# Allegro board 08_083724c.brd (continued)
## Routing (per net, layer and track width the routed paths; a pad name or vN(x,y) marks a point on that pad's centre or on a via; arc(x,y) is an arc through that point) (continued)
VDD_EXT: length 164.8
  TOP w0.14: U1.T12 v1(40.55,54.22) ; U1.K7 v1(45.35,48.62) ; U1.T10 v1(42.95,54.22) ; U1.T22 v1(32.55,53.42) ; U1.H7 v1(45.35,47.02) U1.G7 ; U1.H16 v1(37.35,47.02) ; U1.T14 v1(38.95,54.22) ; U1.P16 v1(37.35,52.62) ; U1.M7 v1(45.35,51.02) ; U1.P7 v1(45.35,52.62) ; U1.M16 v1(37.35,51.02)
  TOP w0.203: U1.K16 v1(37.35,49.42) ; C62.2 16.64,5.83 U9.A2
  TOP w0.305: C1.2 45.25,24.22 v1(45.25,25.1) ; v1(45.25,34.7) 45.04,34.91 C7.2 ; C8.2 37.66,34.91 v1(37.45,34.7) ; U4.21 42.11,4.75 41.98,4.61
  TOP w0.381: C62.2 16.32,8.17 TP23.1 ; v2(17.78,1.17) 18.1,1.49 R155.1 ; R154.1 v2(32.65,18.08) ; R66.1 v2(7.57,6.02)
  TOP w0.508: C54.2 22.15,40.68 v2(22.15,39.83) ; v2(75.79,60.12) C96.1 75.14,60.82 74.69,60.37 U15.4 ; v2(63.55,63.4) 63.58,63.42 v2(64.4,63.42) 64.41,63.43 R132.1 R133.1 R134.1 R135.1 ; R9.1 v2(27.1,40.78) ; R117.1 v2(60.72,59.11) ; v2(68.17,60.26) C242.1 66.94,59.81 U17.4 ; R96.1 v2(70.69,59.42) ; DS9.A 70.92,63.57 v2(70.56,63.21) R95.1 ; R139.1 v2(52.65,61.63) ; R139.1 R140.1 ; R139.1 R138.1 ; R140.1 R141.1 v2(54.94,61.63) ; R140.1 v2(53.8,61.63) ; R83.1 v2(78.31,26.98) ; 16.46,10.04 P10.2 ; P10.2 18.23,11.81 ; P10.2 16.46,11.81 ; P10.2 18.23,10.04 ; v2(63.14,41) 61.7,41 S2.C1 ; Y2.4 54.69,43.11 C241.2 v2(53.94,43.1) ; R109.2 15.82,20.99 15.82,14.78 ; v2(39.45,4.61) C55.1 C53.1 41.98,4.61 ; DS11.A 62.05,51.46 v2(64.35,51.46) ; R115.1 v2(60.72,62.4) ; DS3.A v2(43.64,13.86) ; R101.1 57.73,43.15 v2(57.47,42.89) ; R137.1 R138.1 ; R137.1 R136.1 49.23,61.7 ; R137.1 50.37,61.65 ; R138.1 v2(51.51,61.63) ; C5.1 v2(41.48,20.52) ; DS6.A 21.65,46.94 v2(21.65,47.32) ; R81.1 v2(75.64,29.76) ; v2(12.14,6.53) C32.2 11.39,6.51 U19.5 ; R17.1 39.96,5.38 v2(39.45,5.38) ; R39.1 v2(64.09,31.04) ; DS4.A v2(45.29,13.86) ; S2.C2 v2(71.63,40.69) ; v2(14.74,55.93) 16.24,55.93 DS5.A ; v2(22.15,52.91) 22.15,53.63 C58.2 ; DS2.A v2(41.99,13.86) ; R8.1 v2(27.2,44.88)
  L6_PWR1 w0.508: P10.2 18.23,11.81 ; P10.2 18.23,10.04 ; P10.2 16.46,11.81 ; P10.2 16.46,10.04
  BOTTOM w0.14: U3.F12 v1(37.45,25.1) ; U10.N4 U10.P3
  BOTTOM w0.175: U10.P5 36.4,13.71 35.92,13.24 U10.N4
  BOTTOM w0.203: 26.31,10.58 26.29,10.6 U8.14 ; U7.14 29.53,18.09 29.55,18.07 ; v1(37.35,51.02) 37.17,51.02 36.44,50.28 C170.1 37.23,49.42 v1(37.35,49.42)
  BOTTOM w0.229: U10.N4 v1(35.92,12.71) ; U10.P3 v1(35.42,14.39) ; U10.P5 v1(36.42,14.39)
  BOTTOM w0.305: v1(37.45,25.1) 37.45,23.19 C3.2 ; U3.G4 v1(38.75,31.5) ; U3.G9 v1(38.75,28.3) ; U13.8 v2(74.33,19.19) ; U3.T4 v1(43.95,31.5) ; U5.D1 17.77,42.33 ; U5.B4 v2(22.15,39.83) ; U3.T9 v1(43.95,28.3) ; R123.1 v2(74.31,55.68) ; U3.F1 v1(37.45,34.7) ; U29.14 78.23,30.61 78.57,30.27 ; U3.U1 v1(45.25,34.7) ; U22.21 61.15,22.65 C254.1 ; U5.E4 21.65,44.75 ; U22.17 57.72,26.46 C256.1 ; R113.1 v2(74.75,56.95) ; v2(66.88,53.14) 66.88,53.61 66.57,53.91 U21.4 ; U3.U12 v1(45.25,25.1) ; R159.1 v2(60.66,56.31) ; C167.1 45.35,50.78 v1(45.35,51.02) ; R127.1 67.77,56.28 68.07,56.58 U18.5 69.62,56.58 69.93,56.89 69.93,57.83 C125.1 ; U13.1 78.23,12.83 78.54,13.14 C90.1
  BOTTOM w0.33: U6.B4 v2(22.15,52.91)
  BOTTOM w0.508: C253.1 62.43,22.91 R207.2 ; C253.1 C254.1 ; C253.1 v2(63.32,22.92) ; v2(21.65,47.32) C57.2 21.65,44.76 ; R129.1 v2(69.42,54) ; v2(15.71,42.33) C56.2 16.51,42.33 17.77,42.33 ; P10.2 18.23,10.04 ; P10.2 16.46,10.04 ; P10.2 16.46,11.81 ; P10.2 18.23,11.81 ; v2(30.01,18.86) C59.1 29.55,18.07 ; R47.1 v2(26.56,54.79) ; R14.1 v2(79.71,59.29) ; R48.1 v2(26.56,55.93) ; v2(26.77,11.37) C60.1 26.31,10.58 ; E3.2 53.77,52.36 C164.1 55.91,52.16 v2(57.19,52.16) ; R18.1 v2(13.6,41.32) ; C125.1 v2(69.18,57.84) ; v2(64.57,12.5) C262.1 63.68,12.52 Y4.4 Y4.1 ; C256.1 C255.1 v2(59,25.96) ; R20.1 v2(23.18,36.11) ; R46.1 v2(14.74,55.93) ; C137.1 v2(64.35,51.46) ; v1(32.55,53.42) 32.53,53.39 C171.1 ; 78.57,30.27 C87.1 v2(79.45,31.04) 79.71,31.29 R4.1 ; JP2.1 v2(79.71,45.19) R10.1 ; R44.1 v2(14.74,53.9) ; R145.1 v2(13.6,42.35) ; R38.1 v2(17.03,36.11) ; C90.1 v2(79.45,12.39)
  vias: v1(36.92,8.21) v2(14.55,10.72) v2(14.55,9.96) v2(14.55,9.19) v2(14.55,8.43) v2(15.32,10.72) v2(15.32,9.96) v2(15.32,9.19) v2(15.32,8.43) v2(23.77,50.52) v2(23.77,49.91) v2(26.24,48.98) v2(63.13,40.12)
VDD_INPUT: length 1.7
  BOTTOM w0.254: v2(6.43,43.1) 6.74,43.42 U2.1
  vias: v2(2.24,43.36) v2(2.24,42.6) v2(2.24,41.83) v2(3,43.36) v2(6.43,51.87) v2(6.93,51.87) v2(7.44,51.87) v2(7.95,51.87) v2(10.87,42.72) v2(10.87,41.96) v2(11.63,42.72) v2(11.63,41.96) v2(48.97,23.93) v2(48.97,23.29) v2(49.61,23.93) v2(49.61,23.29)
VDD_INT: length 78.6
  TOP w0.14: U1.J12 v1(40.55,48.62) ; U1.P10 v1(42.95,52.62) ; v1(43.75,51.02) U1.M9 v1(42.95,50.22) ; U1.P12 v1(40.55,52.62) ; U1.P15 v1(38.15,52.62) ; U1.K15 v1(38.15,49.42) ; U1.P8 v1(44.55,52.62) ; U1.R12 v1(40.55,53.42) ; U1.K8 v1(44.55,49.42) ; U1.J8 v1(44.55,48.62) ; U1.K13 v1(39.75,49.42) ; U1.M13 v1(39.75,51.02) ; U1.L15 v1(38.15,50.22) ; U1.R8 v1(44.55,53.42) ; U1.R15 v1(38.15,53.42) ; U1.N8 v1(44.55,51.82) ; U1.K9 v1(43.75,49.42) ; U1.R9 v1(43.75,53.42) ; U1.M8 v1(44.55,51.02) ; U1.T8 v1(44.55,54.22) ; U1.P13 v1(39.75,52.62) ; U1.M15 v1(38.15,51.02) ; U1.K14 v1(38.95,49.42) ; U1.J14 v1(38.95,48.62) ; U1.R14 v1(38.95,53.42) ; U1.P11 v1(42.15,52.62) ; U1.R11 v1(42.15,53.42) ; U1.J11 v1(41.35,48.62) ; U1.J9 v1(43.75,48.62) ; U1.L8 v1(44.55,50.22) ; U1.M12 v1(40.55,51.02) ; U1.R10 v1(42.95,53.42) ; U1.P9 v1(43.75,52.62) ; U1.M14 v1(38.95,51.02) ; U1.K12 v1(41.35,49.42) ; U1.N15 v1(38.15,51.82) ; U1.P14 v1(38.95,52.62) ; U1.J15 v1(38.15,48.62) ; U1.R13 v1(39.75,53.42)
  TOP w0.305: v1(47.32,62.41) 46.93,62.02 C190.1
  TOP w0.508: C185.1 v2(53.77,58.87) ; C193.1 v2(31.54,56.07) ; C192.1 v2(31.54,54.57) ; v2(32.23,60.63) 32.23,61.13 32.74,61.64 C184.1 33.24,61.62 C187.1 ; v2(51.27,53.99) C188.1 C191.1 ; P7.2 25.09,27.48 ; P7.2 25.09,25.71 ; P7.2 23.32,27.48 ; P7.2 23.32,25.71 ; R131.2 15.38,24.69 15.89,25.2 20.65,25.2 ; C194.1 v2(31.54,57.58) ; C186.1 v2(53.77,57.2) ; C190.1 48.06,61.57 C189.1 v2(48.07,62.29) ; 20.65,27.99 15.89,27.99 15.38,28.5 R125.2 ; C206.1 v2(31.55,58.98)
  L7_PWR2 w0.508: P7.2 25.09,27.48 ; P7.2 23.32,25.71 ; P7.2 25.09,25.71 ; P7.2 23.32,27.48
  BOTTOM w0.14: v1(42.95,50.22) 42.95,50.14 C215.1
  BOTTOM w0.305: v1(47.32,62.41) 46.93,62.02 C190.1
  BOTTOM w0.508: C194.1 v2(31.54,57.58) ; C190.1 48.06,61.57 C189.1 v2(48.07,62.29) ; C195.1 v2(26.85,59.36) ; P7.2 25.09,25.71 ; P7.2 25.09,27.48 ; P7.2 23.32,25.71 ; P7.2 23.32,27.48 ; C186.1 v2(53.77,57.2) ; C206.1 v2(31.55,58.98) ; C193.1 v2(31.54,56.07) ; v2(32.23,60.63) C198.1 31.2,61.13 31.71,61.64 C184.1 34.34,61.64 C187.1 ; C185.1 v2(53.77,58.87) ; C197.1 v2(26.85,57.84) ; C188.1 v2(51.27,53.99) ; C192.1 v2(31.54,54.57)
  vias: v2(24.97,31.17) v2(24.97,30.4) v2(24.97,29.64) v2(24.97,28.88) v2(25.73,31.17) v2(25.73,30.4) v2(25.73,29.64) v2(25.73,28.88)
VDD_LPDD4_IO: length 115.8
  TOP w0.14: U1.E8 v1(44.55,44.62) ; U1.E11 v1(42.15,44.62) ; U1.G11 v1(42.15,47.02) ; U1.E13 v1(39.75,44.62) ; U1.F15 v1(38.15,46.22) ; U1.E12 v1(40.55,44.62) ; U1.E9 v1(43.75,44.62) ; U1.D13 v1(39.75,43.82) ; U1.F9 v1(43.75,46.22) ; U1.G9 v1(43.75,47.02) ; U1.D14 v1(38.95,43.82) ; U1.F8 v1(44.55,46.22) ; U1.D10 v1(42.95,43.82) ; U1.G15 v1(38.15,47.02) ; U1.G12 v1(40.55,47.02) ; U1.G14 v1(38.95,47.02) ; U1.E15 v1(38.15,44.62) ; U1.F14 v1(38.95,46.22) ; U1.E14 v1(38.95,44.62) ; U1.D11 v1(42.15,43.82) ; U1.G8 v1(44.55,47.02) ; U1.G13 v1(39.75,47.02) ; U1.D9 v1(43.75,43.82) ; U1.F10 v1(42.95,46.22) ; U1.E10 v1(42.95,44.62) ; U1.G10 v1(42.95,47.02)
  TOP w0.203: v1(42,34.7) 42,35.34 C16.2 ; v1(40.05,25.1) 40.05,24.46 C17.2 ; v1(40.7,34.7) 40.7,35.34 C18.2 ; v1(42,25.1) 42,25.43 C11.2
  TOP w0.305: R148.2 43.01,34.99 v1(43.3,34.7) ; 44.92,30.4 45.21,30.7 v1(45.25,30.7) ; v1(45.25,29.1) 45.21,29.1 44.92,29.39 ; R149.2 39.69,34.99 v1(39.4,34.7) ; v1(42,33.1) 41.5,33.1 C117.2 41.2,33.1 v1(40.7,33.1)
  TOP w0.508: 1.98,11.81 2.87,10.92 ; 2.87,10.92 3.76,11.81 ; 2.87,10.92 3.76,10.04 ; 2.87,10.92 1.98,10.04 ; R16.1 v2(33.35,29.72) ; C14.1 v2(37.8,20.52) ; C146.1 v2(45.03,20.52) ; R106.2 4.39,20.99 4.39,14.78
  BOTTOM w0.14: U3.F10 v1(37.45,26.7) ; U3.N10 v1(42.65,26.7) ; U3.K10 v1(40.05,26.7) ; U3.U8 v1(45.25,29.1) ; U3.AA10 v1(47.85,26.7) ; U3.F8 v1(37.45,29.1) ; U3.AA8 v1(47.85,29.1) ; U3.R8 v1(43.3,28.3) ; U3.B10 v1(34.85,26.7) ; U3.R12 v1(43.3,25.1) ; U3.B8 v1(34.85,29.1) ; U3.N3 v1(42,33.1) ; U3.W8 v1(46.55,29.1) ; U3.H8 v1(39.4,29.1) ; U3.U3 v1(45.25,33.1) ; U3.U10 v1(45.25,26.7) ; U3.D8 v1(36.15,29.1)
  BOTTOM w0.305: U3.R1 v1(43.3,34.7) 43.3,35.34 43.77,35.81 C50.2 ; C22.2 40.84,34.83 v1(40.7,34.7) U3.K1 ; C101.2 C102.2 49.73,27.86 49.36,27.5 v1(48.5,27.5) U3.AB9 ; U3.D1 v1(36.15,34.7) 36.15,35.69 36.03,35.81 C162.2 ; U3.R5 v1(43.3,30.7) ; U3.D5 v1(36.15,30.7) ; C152.2 42,23.17 v1(42,25.1) U3.N12 ; C23.2 41.87,34.83 v1(42,34.7) U3.N1 ; U3.K12 v1(40.05,25.1) 40.05,23.19 C153.2 ; U3.B5 v1(34.85,30.7) ; 44.15,23.16 44.15,23.8 43.3,24.64 v1(43.3,25.1) ; U3.H12 v1(38.75,25.1) 38.75,23.22 C154.2 ; U3.W12 v1(46.55,25.1) 46.55,23.16 C150.2 ; C155.2 36.15,23.16 v1(36.15,25.1) U3.D12 ; U3.F3 v1(37.45,33.1) ; U3.AA5 v1(47.85,30.7) ; U3.AB4 v1(48.5,32.3) 49.49,32.3 49.86,31.93 C98.2 C52.2 ; U3.A9 v1(34.2,27.5) 33.72,27.5 33.35,27.86 C157.2 ; U3.AA3 v1(47.85,32.3) ; U3.K3 v1(40.7,33.1) ; C51.2 46.68,35.73 46.55,35.6 v1(46.55,34.7) U3.W1 ; C49.1 41.04,40.5 C115.1 41.41,40.5 C46.1 v1(42.24,40.93) ; U3.H1 v1(39.4,34.7) 39.4,35.34 38.93,35.81 C21.2 ; U3.U5 v1(45.25,30.7) ; U3.F5 v1(37.45,30.7) ; U3.B3 v1(34.85,32.3) ; U3.H5 v1(39.4,30.7) ; U3.W5 v1(46.55,30.7) ; U3.A4 v1(34.2,32.3) 33.72,32.3 33.35,31.93 C160.2
  BOTTOM w0.508: C102.2 C103.2 C100.2 C98.2 ; C156.2 C157.2 C158.2 C159.2 C160.2 C161.2 ; 2.87,10.92 3.76,10.04 ; 2.87,10.92 3.76,11.81 ; 2.87,10.92 1.98,11.81 ; 2.87,10.92 1.98,10.04 ; v2(52.15,38.15) 50.62,39.68 R150.1
  vias: v2(5.69,11.59) v2(5.69,10.89) v2(5.69,10.19) v2(6.39,11.59) v2(6.39,10.89) v2(6.39,10.19) v2(7.09,11.59) v2(7.09,10.89) v2(7.09,10.19) v2(30.42,38.4) v2(30.42,37.39) v2(52.15,37.13)
VDD_SOM: length 0.8
  BOTTOM w0.508: R164.1 v2(12.4,57.07)
  vias: v2(2.71,66.33) v2(2.71,65.63) v2(2.71,64.93) v2(3.41,66.33) v2(3.41,65.63) v2(3.41,64.93) v2(4.11,66.33) v2(4.11,65.63) v2(4.11,64.93)
_N14: length 18.4
  TOP w0.14: U1.K10 v1(42.95,49.42) ; U1.K11 v1(42.15,49.42) ; U1.M10 v1(42.15,51.02) ; U1.M11 v1(41.35,51.02)
  L3_SIG1 w0.267: v1(42.15,49.42) 42.15,49.59 42.56,50.01 42.56,50.6 v1(42.15,51.02)
  L8_SIG3 w0.267: v1(42.15,49.42) v1(42.95,49.42) ; v1(41.35,51.02) v1(42.15,51.02) 42.99,51.02 43.38,50.63 44.93,50.63 45.34,50.22 v1(46.15,50.22)
  BOTTOM w0.508: E3.1 52.02,52.34 C26.1 51.82,49.95 C27.1 49.98,50.22 v1(46.15,50.22)
_N15: length 4.7
  TOP w0.14: R143.2 53.29,51.6 C25.1 55.76,51.6 55.9,51.47 v2(55.9,50.93)
  BOTTOM w0.14: R158.1 56.85,50.8 56.71,50.93 v2(55.9,50.93)
_N16: length 6.6
  TOP w0.14: R142.1 54.3,48.06 C24.1 54.69,47.68 56.84,47.68 57.8,48.63 v2(57.8,48.73)
  BOTTOM w0.14: v2(57.8,48.73) 56.98,48.73 56.85,48.87 R158.2
_N31: length 5.8
  TOP w0.14: U1.R22 v1(32.55,52.62)
  BOTTOM w0.508: v1(32.55,52.62) 32.3,52.37 C29.1 30.42,52.37 29.91,51.85 C28.1 27.85,51.8 E4.1
_N36: length 16.4
  TOP w0.14: U1.F12 v1(40.55,46.22)
  L6_PWR1 w0.229: v1(40.55,46.22) 41.26,46.22 42.46,45.02 45.53,45.02 45.75,44.8 45.75,42.74 45.88,42.62 47.2,42.62 47.35,42.46 47.35,41.98 47.52,41.82 51.71,41.82 v2(52.65,40.88)
_N50: length 3.5
  BOTTOM w0.14: JP2.2 79.71,48.56 79.2,49.07 P5.1
_N51: length 1.7
  BOTTOM w0.14: P5.10 76.78,55.68 JP1.2
_N72: length 6.1
  TOP w0.14: R153.1 29.47,46.6 30.66,46.6 32.68,48.62 33.35,48.62 U1.K21
_N74: length 4.7
  TOP w0.14: TP24.1 30.66,50.24 34.18,50.24 U1.M20
_N82: length 4.7
  BOTTOM w0.14: R43.2 R45.1 18.75,52.5 U6.B2
_N89: length 10.5
  TOP w0.14: v2(34.49,20.05) 34.49,20.05 R52.2
  L3_SIG1 w0.114: v2(34.49,20.05) 36.33,18.21 36.33,15.86 37.34,14.86 37.34,12.66 v1(36.92,12.24)
  BOTTOM w0.14: U10.M6 v1(36.92,12.24)
_N100: length 4.2
  TOP w0.305: v1(34.92,8.21) 34.54,8.21 34.24,7.91 34.24,6.45 35.18,5.51 C64.2
_N101: length 2.1
  BOTTOM w0.14: R50.1 29.3,19.01 29.3,18.77 29.02,18.49 U7.13
_N102: length 14
  TOP w0.14: v2(33.48,20.12) 33.48,19.24 R52.1
  L5_SIG2 w0.114: v2(28.28,14.27) 32.08,14.27 33.48,15.67 v2(33.48,20.12)
  BOTTOM w0.14: v2(28.28,14.27) 28.28,16.04 27.85,16.47 U7.1
_N105: length 2.4
  BOTTOM w0.14: U8.13 25.78,11 26.06,11.28 26.06,12.06 26.23,12.23 R51.1
_N108: length 13.5
  L8_SIG3 w0.114: v1(35.42,6.74) 28.56,6.74 28.14,7.16 v2(25.04,7.16)
  BOTTOM w0.14: U10.A3 v1(35.42,6.74) ; U8.1 24.62,8.91 25.04,8.49 v2(25.04,7.16)
_N109: length 2.7
  TOP w0.14: U19.4 12.97,3.16 R57.2 R60.2
_N110: length 16.7
  L8_SIG3 w0.114: v1(35.92,6.4) 35.9,6.38 28.29,6.38 27.99,6.68 23.36,6.68 v2(22.88,7.16)
  BOTTOM w0.14: U8.4 23.42,8.96 22.88,8.42 v2(22.88,7.16) ; U10.A4 v1(35.92,6.4)
_N111: length 18
  L5_SIG2 w0.114: v2(22.08,11.64) 24.4,11.64 26.62,9.42 32.56,9.42 34.82,7.16 36,7.16 v1(36.42,6.74)
  BOTTOM w0.14: v2(22.08,11.64) 22.08,11.14 22.22,11 U8.8 ; U10.A5 v1(36.42,6.74)
_N112: length 15.6
  L5_SIG2 w0.114: v1(34.92,7.71) 32.8,9.83 26.82,9.83 24.4,12.26 v2(24.4,13.32)
  BOTTOM w0.14: U8.11 24.22,12.51 24.4,12.69 v2(24.4,13.32)
_N113: length 18.4
  TOP w0.14: U9.B1 15.87,4.51 15.32,5.07 v1(15.32,5.38)
  L3_SIG1 w0.114: v2(24.4,14.47) 23.63,14.47 15.32,6.15 v1(15.32,5.38)
  BOTTOM w0.14: U8.12 24.62,12.14 25.1,12.62 25.1,13.77 v2(24.4,14.47)
_N114: length 11.9
  TOP w0.14: U9.A1 16.24,5.38 v1(16.23,5.38)
  L3_SIG1 w0.114: v1(16.23,5.38) 17.25,6.4 18.87,6.4 23.19,10.72 v2(23.19,12.12)
  BOTTOM w0.14: v2(23.19,12.12) 23.42,11.89 U8.9
_N115: length 12.6
  TOP w0.14: U9.E1 16.02,3.1 v1(15.76,3.1)
  L3_SIG1 w0.114: v1(15.76,3.1) 16.17,2.69 18.21,2.69 18.85,3.33 18.85,3.91 22.99,8.05 v2(23.51,8.05)
  BOTTOM w0.14: U8.3 23.82,8.36 v2(23.51,8.05)
_N116: length 16.6
  TOP w0.14: U9.D1 16.13,3.61 v1(15.76,3.61)
  L3_SIG1 w0.114: v2(25.87,8.93) 25.64,8.5 19.51,2.37 15.79,2.37 15.27,2.9 15.27,3.49 15.38,3.61 v1(15.76,3.61)
  BOTTOM w0.14: v2(25.87,8.93) 25.87,9.63 25.69,9.8 U8.16
_N117: length 19.9
  TOP w0.14: 16.24,4.11 v1(15.78,4.11)
  L3_SIG1 w0.114: v2(26.82,14.64) 26.82,13.87 26.49,13.54 25.5,13.54 24.71,12.75 22.43,12.75 15.78,6.11 v1(15.78,4.11)
  BOTTOM w0.14: v2(26.82,14.64) 26.82,15.56 27.05,15.8 U7.3
_N118: length 21.2
  L3_SIG1 w0.114: v1(16.64,3.71) 16.29,3.71 16.18,3.83 16.18,4.62 17.47,5.92 19.09,5.92 25.54,12.37 26.11,12.37 27.36,13.61 27.36,14.82 v2(29.22,16.69)
  BOTTOM w0.14: v2(29.22,16.69) 29.22,17.07 29,17.29 U7.16
_N119: length 10.2
  L8_SIG3 w0.114: v1(17.04,3.71) 17.04,2.9 17.73,2.21 24.28,2.21 v2(25.1,1.39)
  BOTTOM w0.14: R53.1 v2(25.1,1.39)
_N121: length 2.2
  TOP w0.14: P6.5 v2(25.3,4)
  BOTTOM w0.14: R53.2 25.1,3.79 v2(25.3,4)
_N123: length 11.8
  TOP w0.14: U9.C4 v1(17.86,4.11)
  L5_SIG2 w0.114: v2(27.38,1.39) 26.11,2.67 19.68,2.67 18.24,4.11 v1(17.86,4.11)
  BOTTOM w0.14: R54.1 v2(27.38,1.39)
_N124: length 8
  TOP w0.14: v1(17.86,3.61) 17.55,3.61 U9.D4
  L5_SIG2 w0.114: v1(17.86,3.61) 18.19,3.61 19.48,2.31 22.91,2.31 v2(23.83,1.39)
  BOTTOM w0.14: R55.1 v2(23.83,1.39)
_N125: length 6.6
  TOP w0.14: v1(17.86,3.1) 17.66,3.1 U9.E4
  L5_SIG2 w0.114: v2(22.56,1.39) 22.08,1.87 19.09,1.87 v1(17.86,3.1)
  BOTTOM w0.14: R58.1 v2(22.56,1.39)
_N126: length 15.7
  TOP w0.14: v1(17.49,5.37) 17.44,5.32 U9.A4
  L5_SIG2 w0.114: v2(29.92,1.39) 27.86,3.45 21.39,3.45 19.96,4.88 19.38,4.88 18.44,5.82 17.78,5.82 17.67,5.7 v1(17.49,5.37)
  BOTTOM w0.14: R56.1 v2(29.92,1.39)
_N127: length 14.4
  TOP w0.14: U9.B4 17.69,4.51 17.86,4.69 17.86,5.19 v1(18.05,5.38)
  L5_SIG2 w0.114: v2(28.65,1.39) 26.97,3.07 21.11,3.07 19.89,4.29 18.77,4.29 18.05,5.02 v1(18.05,5.38)
  BOTTOM w0.14: R59.1 v2(28.65,1.39)
_N128: length 3.2
  TOP w0.14: R57.1 14.42,3.61 v2(14.81,3.86)
  L5_SIG2 w0.114: v2(14.81,3.86) 15.46,4.51 v1(16.64,4.51)
_N130: length 2.4
  TOP w0.14: P6.7 v2(23.1,4)
  BOTTOM w0.14: v2(23.1,4) 23.38,3.72 23.38,3.54 R55.2
_N131: length 2.3
  TOP w0.14: P6.8 v2(22,4)
  BOTTOM w0.14: R58.2 22,3.64 v2(22,4)
_N132: length 30.3
  TOP w0.14: v2(7.57,3.23) R66.2 7.58,4.11 9.09,4.11
  TOP w0.508: P6.10_1 P6.10_2 21.06,15.51 v2(21.03,15.48)
  L3_SIG1 w0.114: v2(7.57,3.23) 10.49,3.23 14.81,7.54 16.21,7.54 21.03,12.37 v2(21.03,15.48)
_N133: length 2.5
  TOP w0.14: P6.2 v2(28.6,3.99)
  BOTTOM w0.14: R59.2 28.6,3.14 v2(28.6,3.99)
_N140: length 2.2
  TOP w0.14: P6.3 v2(27.5,4)
  BOTTOM w0.14: v2(27.5,4) 27.5,3.21 R54.2
_N144: length 2.2
  TOP w0.14: P6.1 v2(29.7,4)
  BOTTOM w0.14: R56.2 29.7,3.31 v2(29.7,4)
_N147: length 4.5
  BOTTOM w0.14: R49.1 R46.2 19.13,55.93 U6.D2
_N177: length 5.2
  TOP w0.14: U1.K22 32.47,49.02 30.75,47.29 TP27.1 29.48,47.99 29.21,47.99 R11.1
_N243: length 13.4
  TOP w0.508: v2(73.24,58.22) S4.3 S4.4
  BOTTOM w0.14: v2(73.24,58.22) 72.53,57.51 R113.2 72.16,56.58 U18.1
_N244: length 2.4
  TOP w0.305: R160.1 DS11.C
_N245: length 1.5
  BOTTOM w0.14: R129.2 67.65,54.03 67.26,54.41 U21.3
_N246: length 1.5
  BOTTOM w0.14: U21.6 63.45,54.41 R130.1
_N247: length 3.1
  BOTTOM w0.14: U18.4 67.82,55.28 R127.2 67.45,54.91 U21.2
_N248: length 1.5
  BOTTOM w0.14: C127.1 63.32,54.91 U21.7
_N254: length 2.6
  BOTTOM w0.203: 7.44,58.86 U20.5
  BOTTOM w0.254: R167.2 7.44,58.86
  BOTTOM w0.381: R167.2 R105.1
_N255: length 3.2
  BOTTOM w0.203: U20.6 7.94,58.22 8.14,58.42 9.39,58.42 R107.1
  BOTTOM w0.381: R168.2 10.49,58.21 R107.1
_N256: length 3.2
  BOTTOM w0.203: R111.2 4.99,58.43 6.29,58.43 6.44,58.28 U20.3
  BOTTOM w0.381: R169.2 3.89,58.21 R111.2
_N257: length 2.6
  BOTTOM w0.203: 6.94,58.86 U20.4
  BOTTOM w0.254: R166.2 6.94,58.86
  BOTTOM w0.381: R165.1 R166.2
_N258: length 1.4
  BOTTOM w0.203: U20.10 7.44,54.68 R170.2
_N259: length 1.4
  BOTTOM w0.203: U20.11 6.94,54.68 C250.1
_N260: length 7.2
  L10_SIG4 w0.381: v2(5.61,57.17) 5.61,59.21 v2(4.58,60.24)
  BOTTOM w0.381: U20.2 v2(5.61,57.17) 4.81,57.17 R111.1 3.89,57.21 R163.2
  BOTTOM w0.508: R165.2 v2(4.58,60.24)
_N261: length 7.2
  L10_SIG4 w0.381: v2(9.79,60.24) 8.76,59.21 v2(8.76,57.17)
  BOTTOM w0.381: U20.7 v2(8.76,57.17) 9.56,57.17 R107.2 10.49,57.21 R164.2
  BOTTOM w0.508: R105.2 v2(9.79,60.24)
_N282: length 3.5
  BOTTOM w0.14: P4.1 79.2,35.36 79.71,34.85 R4.2
_N283: length 1.7
  BOTTOM w0.14: R5.2 76.78,41.58 P4.10
_N287: length 2.4
  TOP w0.305: R102.1 72.9,64.12 DS9.C
_N296: length 1.9
  TOP w0.381: R7.1 26.84,46.02 DS1.C
_N299: length 3.5
  BOTTOM w0.508: P9.1 4.05,13.46 ; P9.1 2.87,14.64 ; P9.1 1.69,13.46
_N308: length 2.4
  BOTTOM w0.305: v2(13.67,29.51) 13.67,28.63 13.07,28.03 U16.9
_N321: length 17
  TOP w0.14: U14.26 v2(65.28,23.41)
  L3_SIG1 w0.114: v2(75.39,16.37) 74.98,16.78 69.26,16.78 65.58,20.45 65.58,23.11 v2(65.28,23.41)
  BOTTOM w0.14: v2(75.39,16.37) 75.63,16.61 U13.10
_N322: length 19.2
  TOP w0.14: U14.25 v2(64.78,23.91)
  L3_SIG1 w0.114: v2(76.28,16.37) 75.55,17.1 69.39,17.1 65.93,20.56 65.93,23.56 65.57,23.91 v2(64.78,23.91)
  BOTTOM w0.14: v2(76.28,16.37) 76.28,16.38 U13.11
_N323: length 20.8
  TOP w0.14: v2(77.17,16.37) 77.11,16.37 76.58,16.9 R89.2 ; U14.24 v2(65.28,24.41)
  L3_SIG1 w0.114: v2(77.17,16.37) 76.11,17.43 69.51,17.43 66.24,20.69 66.24,23.99 65.82,24.41 v2(65.28,24.41)
  BOTTOM w0.14: v2(77.17,16.37) 76.93,16.6 U13.12
_N324: length 22.6
  TOP w0.14: U14.23 v2(64.78,24.91) ; v2(77.93,16.37) R88.2
  L3_SIG1 w0.114: v2(77.93,16.37) 76.53,17.77 69.62,17.77 66.56,20.82 66.56,24.22 65.87,24.91 v2(64.78,24.91)
  BOTTOM w0.14: U13.13 77.58,16.72 v2(77.93,16.37)
_N325: length 3
  TOP w0.14: R86.1 R85.2 72.42,22.41 U14.8
_N326: length 1.9
  TOP w0.14: R87.2 72.4,22.91 U14.9
_N327: length 2.2
  TOP w0.14: R90.2 68.56,27.72 U14.18
_N328: length 2.2
  TOP w0.14: U14.19 68.06,27.66 R92.2
_N329: length 2.3
  TOP w0.14: R90.1 DS7.C
_N330: length 2.3
  TOP w0.14: R92.1 DS8.C
_N331: length 5.2
  TOP w0.305: 71.35,20.8 70.35,20.8 70.06,21.1 U14.7
  TOP w0.508: 71.35,20.8 72.24,19.91 C89.1 v2(72.75,19.13) ; R85.1 v2(74.63,22.1)
_N350: length 3
  TOP w0.14: R26.2 42.76,7.42 43.61,7.42 43.91,7.11 U4.18
_N351: length 2
  TOP w0.14: R36.2 44.41,7.41 U4.17
_N352: length 1.8
  TOP w0.14: U4.16 44.91,7.81 R37.2
_N353: length 2.1
  TOP w0.508: DS6.C R42.1
_N354: length 2.1
  TOP w0.14: R37.1 DS4.C
_N355: length 2.1
  TOP w0.14: R36.1 DS3.C
_N356: length 2.1
  TOP w0.14: R26.1 DS2.C
_N361: length 3.8
  BOTTOM w0.305: U16.21 8.66,23.62 7.95,22.91 7.19,22.91 6.55,22.28 v2(6.55,21.77)
_N362: length 3.8
  BOTTOM w0.305: U16.16 11.56,23.62 12.27,22.91 13.03,22.91 13.67,22.28 v2(13.67,21.77)
_N367: length 6.6
  BOTTOM w0.305: R94.1 70.32,2.87 69.46,3.74 D2.1 69.46,5.43 70.05,6.02 70.05,7.42 69.61,7.86 P2.B5
_N368: length 19.4
  TOP w0.305: P2.A5 v2(68.06,12.32)
  BOTTOM w0.305: R93.1 67.29,2.87 68.16,3.74 D2.3 68.16,5.45 67.82,5.79 64.57,5.79 63.14,7.21 63.14,9.17 64.72,10.74 67.46,10.74 68.06,11.34 v2(68.06,12.32)
_N369: length 28.4
  TOP w0.203: 68.45,5.94 P2.SH5 ; P2.SH5 68.81,5.19 ; P2.SH5 69.16,5.94 ; P2.SH5 68.81,6.69 ; P2.SH6 68.81,3.59 ; P2.SH6 68.45,2.84 ; P2.SH6 69.16,2.84 ; P2.SH6 68.81,2.09
  TOP w0.508: 63.69,4.55 P2.SH4 ; P2.SH4 63.69,2.24 ; P2.SH4 65.39,4.55 ; P2.SH4 65.39,2.24 ; 72.23,6.97 P2.SH2 ; P2.SH2 73.93,6.97 ; P2.SH2 73.93,9.28 ; 63.69,6.97 P2.SH1 ; P2.SH1 63.69,9.28 ; P2.SH1 65.39,6.97 ; P2.SH3 73.93,4.55 ; P2.SH3 72.23,2.24 ; P2.SH3 73.93,2.24 ; P2.SH3 72.23,4.55 ; C95.1 75.01,7.49 ; C95.1 75.01,6.32 ; C95.1 74.47,6.91 ; 74.27,8.69 R91.1 ; R91.1 74.92,7.94 ; R91.1 74.92,9.44
_N375: length 3
  BOTTOM w0.305: U16.7 11.61,31.87 C126.1
_N409: length 2.1
  TOP w0.14: Y2.1 57.59,44.48 R101.2
_N410: length 1.4
  TOP w0.14: R114.1 54.66,45.77 Y2.3
_N541: length 5.2
  TOP w0.14: U1.J20 v1(34.15,47.82)
  BOTTOM w0.14: R144.1 30.35,48.23 33.73,48.23 v1(34.15,47.82)
_N544: length 4.5
  TOP w0.14: U1.J21 v1(33.35,47.82)
  BOTTOM w0.14: v1(33.35,47.82) 32.96,47.42 30.8,47.42 R177.1
_N552: length 5.3
  BOTTOM w0.14: R24.2 21.29,37.12 21.43,37.26 22.05,37.26 22.3,37.52 22.3,37.77 22.05,38.02 21.04,38.02 20.65,38.42 U5.A3
_N553: length 5.3
  BOTTOM w0.14: U5.C2 19.65,40.94 19.51,40.8 17.98,40.8 17.73,40.55 17.73,39.8 17.59,39.66 17.36,39.66 17.22,39.8 17.22,40.36 17.03,40.54 16.72,40.54 R22.2
_N554: length 5.4
  BOTTOM w0.14: U5.C3 20.18,40.86 20.18,36.15 R27.1
_N555: length 5.3
  BOTTOM w0.14: U5.D4 22.14,41.83 23.05,41.83 23.19,41.69 23.19,41.21 23.33,41.07 23.57,41.07 23.74,41.24 23.74,42.25 23.88,42.39 24.2,42.39 R29.1
_N556: length 5.3
  BOTTOM w0.14: U5.D2 19.65,42.65 19.45,42.85 17.98,42.85 17.73,43.1 17.73,43.85 17.59,43.99 17.36,43.99 17.22,43.85 17.22,43.29 17.03,43.11 16.74,43.11 R32.1
_N557: length 5.4
  BOTTOM w0.14: R28.1 19.13,46.25 19.13,44.6 19.27,44.46 20,44.46 20.14,44.32 20.14,42.83 U5.D3
_N558: length 5.3
  BOTTOM w0.14: U5.B2 18.62,39.29 18.62,38.02 17.48,36.88 R23.2
_N559: length 5.3
  BOTTOM w0.14: R35.1 16.49,45.91 16.63,46.05 16.83,46.05 16.97,45.91 16.97,45.26 18.65,43.58 U5.E1
_N560: length 5.2
  BOTTOM w0.14: R30.1 24.09,42.98 23.95,43.12 23.95,44.4 23.81,44.54 23.49,44.54 23.32,44.37 23.32,42.99 U5.D5
_N561: length 5.4
  BOTTOM w0.14: U5.E3 20.9,43.58 20.9,44.62 20.51,45.01 19.77,45.01 19.63,45.15 19.63,45.5 19.77,45.64 20.65,45.64 20.83,45.82 20.83,46.27 R34.1
_N562: length 5.2
  BOTTOM w0.14: U5.C4 22.16,40.82 22.81,40.82 23.06,40.56 23.06,39.8 23.32,39.55 23.7,39.55 23.95,39.8 23.95,40.55 24.09,40.69 R33.1
_N563: length 5.3
  BOTTOM w0.14: R31.1 18.53,46.29 18.53,45.95 18.39,45.81 17.74,45.81 17.6,45.67 17.6,45.39 17.74,45.25 18.39,45.25 18.53,45.11 18.53,44.45 U5.E2
_N575: length 6
  TOP w0.14: v1(34.95,42.22) U1.B19
  BOTTOM w0.14: v1(34.95,42.22) 34.55,42.62 32.89,42.62 32.39,43.13 R68.1
_N576: length 1.4
  TOP w0.305: v1(34.2,31.5) R16.2
  BOTTOM w0.14: U3.A5 v1(34.2,31.5)
_N918: length 2.4
  TOP w0.14: R12.1 DS10.C
_N948: length 3.5
  BOTTOM w0.508: P7.1 21.67,27.78 ; P7.1 21.67,25.41 ; P7.1 20.48,26.59
_N949: length 2.4
  BOTTOM w0.305: U16.14 13.07,25.16 13.67,24.56 v2(13.67,23.67)
_N970: length 3.1
  BOTTOM w0.254: C237.1 9.69,43.83 8.78,42.92 U2.2
_N971: length 8
  L3_SIG1 w0.508: v2(6.43,41.83) 7.7,41.83 10.74,44.88 v2(12.22,44.88)
  BOTTOM w0.508: C237.2 v2(12.22,44.88)
_N1006: length 8.9
  TOP w0.14: v2(77.04,42.85) 77.04,39.93 P4.6
  BOTTOM w0.14: JP7.1 75.13,45.7 75.27,45.56 JP8.2 75.27,43.73 76.15,42.85 v2(77.04,42.85)
_N1008: length 1.7
  BOTTOM w0.203: U2.13 6.68,45.02 R116.2
_N1009: length 2.6
  BOTTOM w0.203: R119.1 R120.2 7.18,45.64 U2.14
_N1076: length 15.6
  L8_SIG3 w0.114: v2(77.55,14.47) 78.69,15.61 78.69,19.23 74.98,22.94 v2(74.98,23.8)
  BOTTOM w0.14: U29.6 v2(74.98,23.8) ; v2(77.55,14.47) 76.93,13.85 U13.3
_N1077: length 23.9
  TOP w0.14: v2(76.34,13.51) 76.28,13.45 76.28,12.62 TP16.1
  L8_SIG3 w0.114: v2(76.34,13.51) 75.83,13 75.39,13 75.01,13.39 75.01,14.02 73.25,15.77 73.25,28.82 v2(74.33,29.9)
  BOTTOM w0.14: v2(76.34,13.51) 76.28,13.45 U13.4 ; U29.8 v2(74.33,29.9)
_N1078: length 22.7
  TOP w0.14: v2(75.58,13.51) 75.63,13.46 75.63,12.61 TP17.1
  L8_SIG3 w0.114: v2(76.28,28.75) 76.28,27.74 74.35,25.81 74.35,23.71 73.74,23.1 73.74,15.86 75.58,14.02 v2(75.58,13.51)
  BOTTOM w0.14: v2(75.58,13.51) 75.63,13.46 U13.5 ; U29.11 v2(76.28,28.75)
_N1079: length 14.8
  L8_SIG3 w0.114: v2(76.93,24.09) 79.07,21.95 79.07,15.06 v2(77.58,13.58)
  BOTTOM w0.14: U13.2 v2(77.58,13.58) ; U29.3 v2(76.93,24.09)
_N1103: length 3.5
  BOTTOM w0.508: P10.1 18.53,13.46 ; P10.1 16.17,13.46 ; P10.1 17.35,14.64
_N1111: length 5.3
  BOTTOM w0.14: R25.2 16.62,39.29 17.46,39.29 17.74,39.02 17.74,38.16 17.85,38.05 18.05,38.05 18.19,38.19 18.19,40.13 18.38,40.33 U5.B1
_N1180: length 2.1
  TOP w0.14: R41.1 DS5.C
BMODE0: length 67
  TOP w0.14: S2.1 v2(63.07,43.23) ; U1.F19 v1(34.95,45.42)
  L3_SIG1 w0.114: P12.1 59.04,49.68 59.03,49.68 59.03,49.69 59.03,51.46 57.89,52.6 56.75,52.6 56.74,52.6 56.72,52.6 55.17,52.6 55.07,52.6 51.48,49.02 49.21,49.02 48.95,49.27 48.95,49.53 48.67,49.81 48.43,49.81 48.15,49.53 48.15,49.27 47.9,49.02 46.81,49.02 46.56,48.76 46.56,48.41 46.36,48.21 44.37,48.21 44.15,47.98 44.15,47.62 43.95,47.42 43.61,47.42 43.36,47.17 43.36,46.82 43.15,46.61 42.8,46.61 42.55,46.35 42.55,46 42.36,45.82 35.61,45.82 35.31,45.52 v1(34.95,45.42)
  L5_SIG2 w0.114: v2(63.07,43.23) 60.66,45.64 P12.1
  L8_SIG3 w0.114: v1(71.5,66.38) 71.5,65.93 63.32,57.76 63.32,50.72 P12.1
  BOTTOM w0.14: P8.243 v1(71.5,66.38) ; R1.1 v2(63.07,43.23)
BMODE1: length 78.1
  TOP w0.14: S2.2 v2(71.71,38.15) ; U1.H18 v1(35.75,47.02)
  L3_SIG1 w0.114: v1(35.75,47.02) U1.H18 42.26,47.42 42.55,47.7 42.55,47.98 43.59,49.02 43.89,49.02 44.15,49.28 44.15,49.61 44.35,49.81 46.28,49.81 46.56,50.09 48.03,50.09 48.23,50.29 48.87,50.29 49,50.16 49.61,50.16 49.96,49.81 51.3,49.81 54.86,53.37 58.05,53.37 59.66,51.75 59.66,49.95 59.94,49.68 61.57,49.68 P12.2
  L5_SIG2 w0.114: P12.2 64.54,49.4 66.22,49.4 67.01,48.62 67.01,42.85 v2(71.71,38.15)
  L8_SIG3 w0.114: v1(72,66.55) 72,65.59 66.12,59.72 66.12,50.98 P12.2
  BOTTOM w0.14: P8.245 v1(72,66.55) ; R2.1 v2(71.71,38.15)
BMODE2: length 72
  TOP w0.14: S2.4 v2(63.07,38.15) ; U1.D21 v1(33.35,43.82)
  L3_SIG1 w0.114: v2(63.07,38.15) 56.54,38.15 52.88,41.82 49.98,41.82 49.78,42.01 49.78,42.39 49.56,42.62 49.21,42.62 48.95,42.87 48.95,43.23 48.76,43.42 48.36,43.42 48.15,43.63 48.15,44.03 47.96,44.22 47.53,44.22 47.35,44.39 47.35,44.75 46.28,45.82 45.01,45.82 44.42,45.24 37.87,45.24 37.65,45.02 33.99,45.02 33.75,44.77 33.75,44.5 33.44,44.18 v1(33.35,43.82)
  L5_SIG2 w0.114: v2(63.07,38.15) 64.34,39.42 64.34,46.66 P12.3
  L8_SIG3 w0.114: v1(72.5,66.46) 72.5,62.69 67.51,57.71 67.51,49.83 P12.3
  BOTTOM w0.14: R3.1 v2(63.07,38.15) ; P8.247 v1(72.5,66.46)
BMODE3: length 75.2
  TOP w0.14: S2.8 v2(71.71,43.23) ; U1.F20 v1(34.15,45.42)
  L3_SIG1 w0.114: P12.4 66.85,46.63 62.72,46.63 61.94,47.41 61.94,48.76 61.33,49.36 59.8,49.36 59.35,49.82 59.35,51.62 57.98,52.98 54.92,52.98 51.37,49.43 49.91,49.43 49.5,49.83 48.99,49.83 48.77,50.05 48.33,50.05 48.09,49.81 46.81,49.81 46.56,49.56 46.56,49.25 46.33,49.02 44.42,49.02 44.15,48.74 44.15,48.46 43.92,48.23 43.56,48.23 43.33,48.01 43.33,47.69 43.06,47.42 42.82,47.42 42.55,47.14 42.55,46.89 42.27,46.62 35.59,46.62 35.36,46.38 35.36,46.08 35.1,45.82 34.82,45.82 34.51,45.5 v1(34.15,45.42)
  L5_SIG2 w0.114: P12.4 68.28,46.66 v2(71.71,43.23)
  L8_SIG3 w0.114: v1(73,66.37) 73,60.91 68.28,56.18 P12.4
  BOTTOM w0.14: R6.1 v2(71.71,43.23) ; P8.249 v1(73,66.37)
BP_ALERT_N: length 9.4
  TOP w0.14: v2(30.56,43.93) TP33.1 C33.2 ; U1.G18 v1(35.75,46.22)
  L5_SIG2 w0.114: v2(30.56,43.93) 31.99,43.93 32.28,44.22 34.28,44.22 34.55,44.48 34.55,44.86 34.7,45.02 35.16,45.02 35.35,45.21 35.35,45.82 v1(35.75,46.22)
BP_VREF: length 6
  TOP w0.14: C37.2 TP32.1 52.15,42.09 52.15,42.28 v2(51.83,42.6) ; U1.D2 v1(49.35,43.82)
  L3_SIG1 w0.254: v2(51.83,42.6) 51.83,42.6 51.28,42.6 50.44,43.43 49.73,43.43 v1(49.35,43.82)
CA0_A: length 13
  TOP w0.14: U1.C14 v1(38.95,43.02)
  L3_SIG1 w0.109: v1(38.95,43.02) 38.56,43.41 37.19,43.41 36.96,43.17 36.96,41.12 36.78,40.94 32.33,40.94 32.08,40.69 32.08,39.8 32.46,39.42 32.83,39.42 v3(33.73,38.52)
CA0_A_X: length 10.4
  L3_SIG1 w0.109: v3(33.73,37.52) 34.21,38 38.58,38 39.83,36.75 39.83,34.32 v1(39.4,33.9)
  BOTTOM w0.14: U3.H2 v1(39.4,33.9)
CA0_B: length 6.7
  TOP w0.14: U1.B10 v1(42.95,43.02)
  L3_SIG1 w0.109: v3(46.43,38.52) 44.15,40.81 44.15,41.55 43.89,41.81 43.61,41.81 42.95,42.47 v1(42.95,43.02)
CA0_B_X: length 19
  TOP w0.191: R182.2 v3(46.43,36.76)
  L3_SIG1 w0.109: v3(46.43,36.76) 46.74,36.35 48.9,34.19 48.9,30.18 48.67,29.95 47.49,29.95 47.29,30.15 47.09,30.15 46.88,29.94 46.6,29.94 46.38,30.15 46.06,30.15 45.8,29.9 44.64,29.9 44.53,30.01 44.53,30.73 45.21,31.42 45.21,32.54 44.25,33.5 43.69,33.5 v1(43.3,33.9)
  BOTTOM w0.14: U3.R2 v1(43.3,33.9)
CA1_A: length 6.6
  TOP w0.14: U1.B12 v1(41.35,43.02)
  L3_SIG1 w0.109: v3(39.45,38.52) 40.2,38.52 41.27,39.6 41.27,41.76 40.84,42.19 40.84,42.5 v1(41.35,43.02)
CA1_A_X: length 16.4
  TOP w0.191: R190.2 v3(40.28,37.52)
  L3_SIG1 w0.109: v3(40.28,37.52) 41.01,38.25 41.35,38.25 41.48,38.13 41.48,36.96 41.27,36.75 41.27,29.77 41.02,29.51 40.44,29.51 40.21,29.74 40.21,30.78 40.61,31.19 40.61,32.53 v1(40.05,33.1)
  BOTTOM w0.14: U3.J2 v1(40.05,33.1)
CA1_B: length 15.6
  TOP w0.14: U1.C10 v1(42.15,43.02)
  L3_SIG1 w0.109: v3(45.29,38.52) 43.36,40.45 43.36,41.55 42.56,42.35 42.56,43.32 42.65,43.41 45.59,43.41 45.77,43.59 45.77,44.07 45.64,44.2 41.86,44.2 41.76,44.09 41.76,43.66 42.15,43.27 v1(42.15,43.02)
CA1_B_X: length 10.7
  TOP w0.191: R183.2 v3(45.29,36.76)
  L3_SIG1 w0.109: v3(45.29,36.76) 45.29,35.92 45.44,35.76 46.61,35.76 46.76,35.61 46.76,35.1 47.02,34.85 47.47,34.85 47.57,34.75 47.57,34.39 47.5,34.32 43.07,34.32 v1(42.65,33.9)
  BOTTOM w0.14: U3.P2 v1(42.65,33.9)
CA2_A: length 6.5
  TOP w0.14: U1.C12 v1(40.55,43.02)
  L3_SIG1 w0.109: v1(40.55,43.02) 40.34,42.8 40.34,42.16 40.92,41.58 40.92,41.14 v3(38.3,38.52)
CA2_A_X: length 16.5
  TOP w0.191: v3(38.68,36.63) 38.3,37.02 R189.2
  L3_SIG1 w0.109: v3(38.68,36.63) 36.83,34.78 36.83,34.65 36.3,34.11 36.3,32.8 36.41,32.69 37.8,32.69 38.13,32.36 38.13,32.04 38.26,31.9 39.95,31.9 40.08,31.78 40.08,31.42 39.78,31.11 38.41,31.11 38.33,31.04 38.33,28.85 38.48,28.7 39,28.7 v1(39.4,28.3)
  BOTTOM w0.14: U3.H9 v1(39.4,28.3)
CA2_B: length 7
  TOP w0.14: U1.C11 v1(41.35,43.82)
  L3_SIG1 w0.109: v3(44.15,38.52) 42.85,39.82 42.85,40.92 42.57,41.2 42.57,41.63 41.76,42.44 41.76,43.15 41.35,43.56 v1(41.35,43.82)
CA2_B_X: length 23.3
  TOP w0.191: R184.2 v3(44.15,36.76)
  L3_SIG1 w0.109: v1(43.95,27.5) 44.35,27.1 46.2,27.1 47.16,28.05 49.06,28.05 50.47,29.46 50.47,36.86 49.71,37.62 47.22,37.62 46.91,37.31 44.68,37.31 44.15,36.78 v3(44.15,36.76)
  BOTTOM w0.14: U3.R9 v1(43.95,27.5)
CA3_A: length 8.4
  TOP w0.14: U1.B14 v1(38.95,42.22)
  L3_SIG1 w0.109: v3(34.87,38.52) 34.87,40.39 35.05,40.56 37.18,40.56 37.74,41.13 37.74,42.44 37.93,42.62 38.55,42.62 v1(38.95,42.22)
CA3_A_X: length 15.9
  TOP w0.191: R188.2 v3(34.87,36.76)
  L3_SIG1 w0.109: v1(38.75,26.7) 38.34,27.1 36.3,27.1 35.53,27.86 34.7,27.86 33.99,28.57 33.99,29.64 33.12,31.6 33.12,33.45 33.83,34.16 33.83,35.18 34.66,36 v3(34.87,36.76)
  BOTTOM w0.14: U3.H10 v1(38.75,26.7)
CA3_B: length 8.2
  TOP w0.14: U1.C9 v1(43.75,43.02)
  L3_SIG1 w0.109: v3(48.72,38.52) 48,39.24 47.62,39.24 45.75,41.12 45.75,42.49 45.64,42.6 44.17,42.6 v1(43.75,43.02)
CA3_B_X: length 17.5
  TOP w0.191: R185.2 v3(48.72,36.76)
  L3_SIG1 w0.109: v3(48.72,36.76) 50.09,35.39 50.09,29.62 48.84,28.37 46.56,28.37 46.08,27.89 43.71,27.89 43.54,27.71 43.54,27.11 v1(43.95,26.7)
  BOTTOM w0.14: U3.R10 v1(43.95,26.7)
CA4_A: length 8.1
  TOP w0.14: U1.C13 v1(39.75,43.02)
  L3_SIG1 w0.109: v1(39.75,43.02) 39.34,42.61 39.34,41.22 38.3,40.18 36.14,40.18 35.69,39.73 35.69,38.85 v3(36.02,38.52)
CA4_A_X: length 16.2
  TOP w0.191: R187.2 v3(36.02,36.76)
  L3_SIG1 w0.109: v1(39.4,26.7) 38.21,27.89 36.6,27.89 35.79,28.7 34.72,28.7 34.39,29.03 34.39,29.67 33.48,31.75 33.48,33.35 34.16,34.04 34.16,34.91 v3(36.02,36.76)
  BOTTOM w0.14: U3.H11 v1(39.4,26.7)
CA4_B: length 5.5
  TOP w0.14: U1.B11 v1(41.35,42.22)
  L3_SIG1 w0.109: v3(43,38.52) 42.12,38.52 41.63,39.01 41.63,41.94 v1(41.35,42.22)
CA4_B_X: length 26.2
  TOP w0.191: R186.2 v3(43,36.76)
  L3_SIG1 w0.109: v1(43.95,25.9) 44.34,26.29 48.01,26.29 48.29,26.57 48.29,26.9 48.49,27.1 48.67,27.1 50.83,29.26 50.83,37.03 49.89,37.97 47.12,37.97 46.79,37.64 43.94,37.64 43.06,36.76 v3(43,36.76)
  BOTTOM w0.14: U3.R11 v1(43.95,25.9)
CA5_A: length 7.6
  TOP w0.14: U1.B13 v1(39.75,42.22)
  L3_SIG1 w0.109: v3(37.16,38.52) 36.4,39.29 36.4,39.55 36.53,39.67 38.67,39.67 40.16,41.17 40.16,41.81 v1(39.75,42.22)
CA5_A_X: length 16.6
  TOP w0.191: R179.2 v3(37.16,36.76)
  L3_SIG1 w0.109: v1(39.4,25.9) 39.79,26.29 40.21,26.29 40.46,26.54 40.46,26.82 39.6,27.69 38.84,27.69 37.92,28.6 37.92,30.76 37.59,31.09 37.34,31.09 35.89,32.54 35.89,33.68 35.13,34.44 35.13,34.92 36.07,35.86 36.4,35.86 36.88,36.35 v3(37.16,36.76)
  BOTTOM w0.14: U3.J11 v1(39.4,25.9)
CA5_B: length 6.2
  TOP w0.14: U1.B9 v1(43.75,42.22)
  L3_SIG1 w0.109: v3(47.57,38.52) 44.96,41.14 44.96,41.66 44.78,41.83 44.4,41.83 44.09,42.14 v1(43.75,42.22)
CA5_B_X: length 21.3
  TOP w0.191: R180.2 v3(47.57,36.76)
  L3_SIG1 w0.109: v3(47.57,36.76) 49.71,34.63 49.71,29.77 48.64,28.7 41.83,28.7 41.61,28.47 41.61,27.13 42.44,26.29 42.91,26.29 v1(43.3,25.9)
  BOTTOM w0.14: U3.P11 v1(43.3,25.9)
CARRIER_DETECT*: length 4.4
  TOP w0.14: R102.2 76.25,64.61 P8.262
CK_C_A: length 27.1
  TOP w0.14: U1.A15 v1(38.15,41.42)
  L5_SIG2 w0.107: v1(38.15,41.42) 37.86,41.12 37.86,40.2 37.25,39.59 32.67,39.59 31.78,38.7 31.78,32.58 34.51,29.85 40.29,29.85 40.89,29.25 40.89,28.99 40.49,28.59 40.35,28.59 v1(40.05,28.3)
  BOTTOM w0.14: U3.J9 v1(40.05,28.3)
CK_C_B: length 29.8
  TOP w0.14: U1.A6 v1(46.15,41.42)
  L5_SIG2 w0.107: v1(42.65,28.3) 42.95,28.59 43.09,28.59 43.57,29.07 43.57,29.54 43.8,29.77 51,29.77 51.51,30.28 51.51,33.63 51.28,33.86 50.3,33.86 50.2,33.96 50.2,34.39 50.3,34.5 51.28,34.5 51.51,34.73 51.51,39.8 51.18,40.14 46.14,40.14 45.86,40.42 45.86,41.12 v1(46.15,41.42)
  BOTTOM w0.14: U3.P9 v1(42.65,28.3)
CK_T_A: length 27.1
  TOP w0.14: U1.A16 v1(37.35,41.42)
  L5_SIG2 w0.107: v1(37.35,41.42) 37.65,41.12 37.65,40.29 37.16,39.8 36.53,39.8 36.31,40.02 35.96,40.02 35.74,39.8 35.34,39.8 35.13,40.02 34.77,40.02 34.55,39.8 32.59,39.8 31.57,38.79 31.57,32.5 34.43,29.64 40.21,29.64 40.69,29.16 40.69,29.08 40.41,28.8 40.35,28.8 v1(40.05,29.1)
  BOTTOM w0.14: U3.J8 v1(40.05,29.1)
CK_T_B: length 29.8
  TOP w0.14: U1.A7 v1(45.35,41.42)
  L5_SIG2 w0.107: v1(45.35,41.42) 45.65,41.12 45.65,40.33 46.05,39.93 51.09,39.93 51.3,39.72 51.3,34.81 51.2,34.71 50.22,34.71 49.99,34.48 49.99,33.88 50.22,33.65 51.2,33.65 51.3,33.54 51.3,30.36 50.92,29.98 46.17,29.98 45.93,30.21 45.67,30.21 45.5,30.04 45.18,30.04 45.01,30.21 44.73,30.21 44.49,29.98 43.72,29.98 43.37,29.62 43.37,29.16 43.01,28.8 42.95,28.8 v1(42.65,29.1)
  BOTTOM w0.14: U3.P8 v1(42.65,29.1)
CKE0_A: length 20.5
  TOP w0.14: U1.E16 v1(37.35,44.62)
  L5_SIG2 w0.109: v1(37.35,44.62) 38.56,45.82 40.86,45.82 41.76,44.92 41.76,41.81 41.48,41.53 41.48,31.49 v1(40.72,30.72)
CKE0_A_X: length 2
  TOP w0.191: v1(39.4,32.3) 39.9,31.8 40.72,31.8
  BOTTOM w0.14: U3.J4 v1(39.4,32.3)
CKE0_B: length 25
  TOP w0.14: U1.E7 v1(45.35,44.62)
  L5_SIG2 w0.109: v1(45.35,44.62) 44.96,44.22 43.51,44.22 43.36,44.07 43.36,43.59 43.18,43.41 42.71,43.41 42.55,43.25 42.55,41.27 42.81,41.01 42.81,37.45 42.34,36.98 42.34,35.31 42.52,35.13 44.6,35.13 44.68,35.05 44.68,34.47 44.86,34.29 46.22,34.29 46.33,34.18 46.33,32.05 46.18,31.9 42.09,31.9 41.86,31.67 v1(41.86,30.72)
CKE0_B_X: length 2.1
  TOP w0.191: v1(43.3,31.5) 42.93,31.87 41.93,31.87 41.86,31.8
  BOTTOM w0.14: U3.P4 v1(43.3,31.5)
CKE1_A: length 19.9
  TOP w0.14: U1.C15 v1(38.15,43.02)
  L5_SIG2 w0.109: v1(38.15,43.02) 38.56,43.42 39.13,43.42 39.34,43.64 39.34,44.81 39.55,45.01 39.95,45.01 40.16,44.81 40.16,42.49 41.15,41.5 41.15,31.75 40.28,30.89 40.28,30.43 v1(40.72,30)
CKE1_A_X: length 2.6
  TOP w0.191: R122.1 39.95,30.01 39.95,30.94 v1(39.4,31.5)
  BOTTOM w0.14: U3.J5 v1(39.4,31.5)
CKE1_B: length 23.9
  TOP w0.14: U1.C8 v1(44.55,43.02)
  L5_SIG2 w0.109: v1(44.55,43.02) 44.15,42.61 44.15,40.31 44.78,39.67 44.78,35.99 45.03,35.74 47.96,35.74 48.92,34.77 48.92,31.34 48.67,31.09 42.67,31.09 42.45,30.86 42.45,30.59 v1(41.86,30)
CKE1_B_X: length 2.3
  TOP w0.191: R121.1 42.65,29.98 v1(42.65,31.5)
  BOTTOM w0.14: U3.P5 v1(42.65,31.5)
CS0_A: length 8.8
  TOP w0.14: U1.A17 v1(36.55,41.42)
  L3_SIG1 w0.109: v3(32.59,38.52) 31.75,39.36 31.75,41.17 32.38,41.81 36.16,41.81 v1(36.55,41.42)
CS0_A_X: length 14.9
  TOP w0.191: R192.2 v3(32.59,36.76)
  L3_SIG1 w0.109: v1(38.75,32.3) 37.95,33.1 37.95,35.03 39.24,36.32 39.24,36.83 38.46,37.62 34.54,37.62 33.96,37.03 33.96,36.47 33.6,36.12 33.23,36.12 v3(32.59,36.76)
  BOTTOM w0.14: U3.H4 v1(38.75,32.3)
CS0_B: length 4.7
  TOP w0.14: U1.A5 v1(46.95,41.42)
  L3_SIG1 w0.109: v1(46.95,41.42) 49.84,38.52 v3(49.86,38.52)
CS0_B_X: length 22.9
  TOP w0.191: R181.2 v3(49.86,36.76)
  L3_SIG1 w0.109: v1(43.95,32.3) 43.58,31.93 42.37,31.93 42.27,31.82 42.27,30.89 43.64,29.51 48.82,29.51 49.28,29.97 49.28,34.34 47.02,36.6 47.02,36.93 47.35,37.26 49.36,37.26 v3(49.86,36.76)
  BOTTOM w0.14: U3.R4 v1(43.95,32.3)
CS1_A: length 23.8
  TOP w0.14: U1.A14 v1(38.95,41.42)
  L5_SIG2 w0.109: v1(39.4,33.1) 39.02,32.72 38.46,32.72 38.35,32.61 38.35,31.2 38.24,31.09 36.66,31.09 36.55,31.2 36.55,31.67 36.31,31.9 34.03,31.9 33.83,32.1 33.83,35.51 33.22,36.12 33.22,37.39 33.6,37.77 38.56,37.77 38.95,38.16 v1(38.95,41.42)
  BOTTOM w0.14: U3.H3 v1(39.4,33.1)
CS1_B: length 26.3
  TOP w0.14: U1.A8 v1(44.55,41.42)
  L3_SIG1 w0.109: v1(44.55,41.42) 44.55,41.1 46.99,38.66 46.99,38.3 46.69,38 43.42,38 43.31,37.89 43.31,37.55 43.2,37.44 42.98,37.44 42.87,37.55 42.87,37.89 42.76,38 42.6,38 42.47,37.87 42.47,36.33 42.36,36.22 41.71,36.22 41.61,36.11 41.61,35.75 41.71,35.64 44.57,35.64 44.68,35.54 44.68,35.32 44.57,35.21 41.71,35.21 41.61,35.1 41.61,32.19 41.71,32.08 41.88,32.08 42.49,32.69 42.82,32.69 43.13,32.39 43.48,32.39 43.64,32.54 43.64,32.76 v1(43.3,33.1)
  BOTTOM w0.14: U3.R3 v1(43.3,33.1)
DAI0_PIN01: length 34.4
  TOP w0.14: U1.N17 v1(36.55,51.82)
  L5_SIG2 w0.114: v1(18,66.55) 18.73,67.28 29.01,67.28 29.5,66.79 29.5,64.25 31.19,62.56 34.24,62.56 36.95,59.85 36.95,52.22 v1(36.55,51.82)
  BOTTOM w0.14: P8.29 v1(18,66.55)
DAI0_PIN02: length 36.7
  TOP w0.14: U1.N18 v1(35.75,51.82)
  L5_SIG2 w0.114: v1(35.75,51.82) U1.N18 36.15,50.68 35.31,49.83 34.04,49.83 33.75,49.55 33.75,49.27 33.1,48.62 28.73,48.62 27.38,49.96 26.04,49.96 24.04,51.96 24.04,52.61 18.49,58.16 18.49,60.76 17.27,61.98 17.27,63.8 18.39,64.92 18.39,65.98 18.28,66.09 v1(18,66.09)
  BOTTOM w0.14: v1(18,66.09) 18.24,66.09 18.38,66.24 18.38,66.49 18.5,66.6 P8.31
DAI0_PIN03: length 27.1
  TOP w0.14: U1.P20 v1(34.15,52.62)
  L5_SIG2 w0.114: v1(34.15,52.62) 33.79,52.51 33.5,52.22 27.71,52.22 20.27,59.66 20.27,62.34 v1(19.25,63.36)
  BOTTOM w0.14: v1(19.25,63.36) 18.65,63.96 18.65,66.24 19,66.58 P8.33
DAI0_PIN04: length 34.1
  TOP w0.14: U1.N20 v1(34.15,51.82)
  L5_SIG2 w0.114: v1(34.15,51.82) 34.15,51.27 33.43,50.55 31.39,50.55 30.76,51.18 27.79,51.18 25.83,53.14 24.89,53.14 19.56,58.47 19.56,61.57 18.49,62.64 18.49,63.62 18.93,64.06 19.46,64.06 19.94,64.54 20.22,64.54 20.37,64.69 20.37,66.78 20.19,66.95 19.18,66.95 19,66.77 v1(19,66.09)
  BOTTOM w0.14: P8.35 19.5,66.33 19.25,66.09 v1(19,66.09)
DAI0_PIN05: length 34.5
  TOP w0.14: U1.N19 v1(34.95,51.82)
  L5_SIG2 w0.114: v1(34.95,51.82) U1.N19 35.35,50.72 34.82,50.19 33.93,50.19 33.62,49.87 31.03,49.87 30.46,50.44 26.11,50.44 24.36,52.2 24.36,52.75 18.85,58.26 18.85,61.06 17.75,62.15 17.75,63.84 18.61,64.69 19.15,64.69 19.38,64.92 19.38,66.44 19.49,66.55 v1(20,66.55)
  BOTTOM w0.14: P8.37 v1(20,66.55)
DAI0_PIN06: length 34.7
  TOP w0.14: U1.P17 v1(36.55,52.62)
  L5_SIG2 w0.114: v1(20,66.09) 19.76,66.09 19.63,65.96 19.63,64.77 19.25,64.39 18.77,64.39 18.14,63.75 18.14,62.41 19.23,61.32 19.23,58.33 24.73,52.82 25.7,52.82 27.72,50.8 30.56,50.8 31.17,50.19 33.5,50.19 34.55,51.24 34.55,51.95 34.82,52.22 36.15,52.22 v1(36.55,52.62)
  BOTTOM w0.14: v1(20,66.09) 20,66.09 20.27,66.09 20.38,66.2 20.38,66.65 20.5,66.76 P8.39
DAI0_PIN07: length 31.5
  TOP w0.14: U1.R18 v1(35.75,53.42)
  L5_SIG2 w0.114: v1(20.02,64.06) 19.68,63.72 19.04,63.72 18.85,63.53 18.85,62.79 19.9,61.73 19.9,59.55 27.82,51.64 31.32,51.64 31.55,51.41 33.63,51.41 33.76,51.54 33.76,51.97 34,52.22 34.28,52.22 34.54,52.48 34.54,52.76 34.78,52.99 35.33,52.99 v1(35.75,53.42)
  BOTTOM w0.14: P8.41 21,66.82 20.65,66.47 20.65,64.69 v1(20.02,64.06)
DAI0_PIN08: length 28.4
  TOP w0.14: U1.T18 v1(35.75,54.22)
  L5_SIG2 w0.114: v1(35.75,54.22) 35.36,53.82 34.75,53.82 34.54,53.61 34.54,53.28 34.28,53.02 27.4,53.02 20.62,59.79 20.62,66.21 20.74,66.32 v1(21,66.32)
  BOTTOM w0.14: v1(21,66.32) 21.29,66.32 21.5,66.53 P8.43
DAI0_PIN09: length 28.3
  TOP w0.14: U1.P18 v1(35.75,52.62)
  L5_SIG2 w0.114: v1(35.75,52.62) 36.14,53.01 36.14,54.38 35.89,54.64 33.93,54.64 33.76,54.81 33.76,55.3 33.63,55.42 33.2,55.42 32.94,55.17 32.94,54.79 32.69,54.53 32.18,54.53 31.7,54.05 30.61,54.05 29.24,55.42 28.68,55.42 27.3,56.79 26.64,56.79 25.37,58.06 25.37,59.51 22.38,62.51 22.38,66.44 22.26,66.55 v1(22,66.55)
  BOTTOM w0.14: P8.45 v1(22,66.55)
DAI0_PIN10: length 26.3
  TOP w0.14: U1.R20 v1(34.15,53.42)
  L5_SIG2 w0.114: v1(21.01,64.85) 21.01,59.87 25.5,55.37 26.92,55.37 28.91,53.39 32,53.39 32.44,53.82 33.74,53.82 v1(34.15,53.42)
  BOTTOM w0.14: v1(21.01,64.85) 21.37,64.85 21.51,64.99 21.51,65.84 21.79,66.12 22.28,66.12 22.5,66.33 P8.47
DAI0_PIN11: length 30.3
  TOP w0.14: P8.30 18.25,66.79 18.35,66.69 18.35,65.95 18.25,65.84 18.25,65.83 v1(18,65.58) ; U1.P19 v1(34.95,52.62)
  L3_SIG1 w0.114: v1(18,65.58) 17.61,65.58 17.5,65.47 17.5,64.77 17.86,64.41 17.86,63.1 20.03,60.92 20.03,58.57 23.98,54.62 23.98,53.53 24.89,52.62 31.97,52.62 32.37,52.22 34.55,52.22 v1(34.95,52.62)
DAI0_PIN12: length 30.9
  TOP w0.14: v1(18,65.07) 18.13,65.21 18.26,65.21 18.63,65.58 18.63,66.73 18.75,66.84 P8.32 ; U1.R17 v1(36.55,53.42)
  L3_SIG1 w0.114: v1(36.55,53.42) 36.15,53.02 24.99,53.02 24.3,53.71 24.3,54.86 20.35,58.81 20.35,61.13 18.24,63.25 18.24,64.84 v1(18,65.07)
DAI0_PIN13: length 28.3
  TOP w0.14: P8.34 19.25,66.79 19.35,66.69 19.35,65.95 19.25,65.84 19.25,65.83 v1(19,65.58) ; U1.R19 v1(34.95,53.42)
  L3_SIG1 w0.114: v1(19,65.58) 18.68,65.58 18.57,65.47 18.57,63.42 20.67,61.32 20.67,58.94 26.16,53.45 32.04,53.45 32.4,53.82 34.55,53.82 v1(34.95,53.42)
DAI0_PIN14: length 27.5
  TOP w0.14: U1.T19 v1(34.95,54.22) ; v1(19,65.07) 19.63,65.71 19.63,66.73 19.75,66.84 P8.36
  L3_SIG1 w0.114: v1(34.95,54.22) 34.55,54.62 32.29,54.62 31.76,54.08 26.42,54.08 21.37,59.13 21.37,63.28 20.14,64.52 19.56,64.52 v1(19,65.07)
DAI0_PIN15: length 26.3
  TOP w0.14: v1(20.02,63.55) 19.88,63.68 19.86,63.68 19.64,63.9 19.64,64.21 19.65,64.22 19.65,65.22 20.02,65.59 20.02,65.6 20.35,65.93 20.35,66.69 20.25,66.79 P8.38 ; U1.T20 v1(34.15,54.22)
  L3_SIG1 w0.114: v1(20.02,63.55) 21.01,62.56 21.01,59.05 26.29,53.77 31.9,53.77 32.35,54.22 v1(34.15,54.22)
DAI0_PIN16: length 25.5
  TOP w0.14: P8.40 20.75,66.84 20.63,66.73 20.63,65.71 v1(20,65.07) ; U1.U20 v1(34.15,55.02)
  L3_SIG1 w0.114: v1(20,65.07) 20.29,64.87 21.72,63.45 21.72,59.24 25.61,55.35 29.24,55.35 29.74,55.85 30.28,55.85 30.99,55.14 32,55.14 32.28,55.42 33.75,55.42 v1(34.15,55.02)
DAI0_PIN17: length 24.5
  TOP w0.14: U1.U21 v1(33.35,55.02) ; P8.42 21.25,66.79 21.35,66.69 21.35,65.98 21.21,65.84 v1(21,65.84)
  L5_SIG2 w0.114: v1(21,65.84) 21.35,65.84 21.46,65.72 21.46,61.44 26.47,56.44 27.13,56.44 27.99,55.58 27.99,54.89 29.15,53.73 31.86,53.73 32.28,54.15 33.02,54.15 33.35,54.48 v1(33.35,55.02)
DAI0_PIN18: length 21.4
  TOP w0.14: U1.V22 v1(32.55,55.82) ; v1(21,65.33) 21.25,65.33 21.63,65.71 21.63,66.73 21.75,66.84 P8.44
  L3_SIG1 w0.114: v1(21,65.33) 21.41,65.33 21.54,65.2 21.54,64.44 22.17,63.8 22.17,62.38 26.34,58.22 26.34,57.56 27.18,56.72 30.12,56.72 31.27,55.58 31.78,55.58 32.02,55.82 v1(32.55,55.82)
DAI0_PIN19: length 23.3
  TOP w0.14: P8.46 22.25,66.79 22.34,66.69 22.34,66.26 22.34,66.26 22.34,66.24 22.35,66.24 22.35,65.93 v1(22,65.58) ; U1.U18 v1(35.75,55.02)
  L3_SIG1 w0.114: v1(35.75,55.02) 35.35,55.42 34.78,55.42 34.55,55.64 34.55,56.03 34.36,56.22 34.01,56.22 33.76,56.46 33.76,56.79 33.54,57.02 32.8,57.02 31.7,58.12 27.94,58.12 27.25,58.8 26.72,58.8 22.9,62.62 22.9,64.68 v1(22,65.58)
DAI0_PIN20: length 21.3
  TOP w0.14: P8.48 22.75,67.04 22.68,66.98 22.68,65.76 v1(22,65.07) ; U1.V20 v1(34.15,55.82)
  L3_SIG1 w0.114: v1(34.15,55.82) 33.82,55.89 33.5,56.22 32.15,56.22 31.27,57.1 28.45,57.1 27.1,58.45 26.59,58.45 22.56,62.48 22.56,64.51 v1(22,65.07)
DAI1_PIN01: length 20.7
  TOP w0.14: U1.U22 v1(32.55,55.02)
  L5_SIG2 w0.114: v1(23.5,66.55) 22.91,66.55 22.66,66.3 22.66,64.35 23.01,64 23.01,62.64 25.78,59.87 25.78,58.22 26.82,57.18 27.48,57.18 28.04,56.62 29.51,56.62 31.06,55.07 32.21,55.07 v1(32.55,55.02)
  BOTTOM w0.14: P8.51 v1(23.5,66.55)
DAI1_PIN02: length 20.2
  TOP w0.14: U1.V21 v1(33.35,55.82)
  L5_SIG2 w0.114: v1(33.35,55.82) 32.98,55.71 32.69,55.42 31.29,55.42 29.67,57.05 28.3,57.05 26.19,59.16 26.19,60.25 23.88,62.56 23.88,65.98 23.76,66.09 v1(23.5,66.09)
  BOTTOM w0.14: v1(23.5,66.09) 23.75,66.09 24,66.33 P8.53
DAI1_PIN03: length 23.4
  TOP w0.14: U1.T17 v1(36.55,54.22)
  L5_SIG2 w0.114: v1(36.55,54.22) 36.55,54.49 36.2,54.84 36.2,56 35.98,56.21 32.13,56.21 31.65,56.69 30.51,56.69 29.79,57.4 29.79,58.04 29.62,58.22 28.98,58.22 24.33,62.87 24.33,64.67 24.13,64.87 24.13,66.44 24.24,66.55 v1(24.5,66.55)
  BOTTOM w0.14: P8.55 v1(24.5,66.55)
DAI1_PIN04: length 17.2
  TOP w0.14: U1.Y22 32.28,57.02 v1(32.08,56.82)
  L5_SIG2 w0.114: v1(32.08,56.82) 31.8,57.1 30.6,57.1 30.23,57.47 30.23,58.52 28.91,59.84 28.19,59.84 24.87,63.17 24.87,65.98 24.75,66.09 v1(24.5,66.09)
  BOTTOM w0.14: P8.57 25,66.33 24.75,66.09 v1(24.5,66.09)
DAI1_PIN05: length 16.1
  TOP w0.14: U1.W22 v1(32.55,56.62)
  L5_SIG2 w0.114: v1(25.5,66.55) 25.23,66.55 25.12,66.44 25.12,64.69 30.52,59.3 30.52,58.93 30.52,58.67 31.05,58.14 31.72,58.14 32.55,57.31 v1(32.55,56.62)
  BOTTOM w0.14: P8.59 v1(25.5,66.55)
DAI1_PIN06: length 14.8
  TOP w0.14: U1.AA22 v1(32.55,58.22)
  L5_SIG2 w0.114: v1(25.5,66.09) 25.74,66.09 25.86,65.98 25.86,64.49 30.84,59.51 30.84,58.8 31.18,58.46 31.86,58.46 32.1,58.22 v1(32.55,58.22)
  BOTTOM w0.14: v1(25.5,66.09) 25.75,66.09 26,66.33 P8.61
DAI1_PIN07: length 16
  TOP w0.14: U1.W21 v1(33.35,56.62)
  L5_SIG2 w0.114: v1(26.5,66.55) 26.25,66.55 26.14,66.44 26.14,64.72 31.37,59.49 31.75,59.49 32.08,59.16 32.08,58.93 32.36,58.65 32.69,58.65 32.93,58.41 32.93,57.04 v1(33.35,56.62)
  BOTTOM w0.14: P8.63 v1(26.5,66.55)
DAI1_PIN08: length 15.6
  TOP w0.14: U1.Y21 v1(33.35,57.42)
  L5_SIG2 w0.114: v1(26.5,66.09) 26.76,66.09 26.87,65.98 26.87,64.52 31.22,60.17 31.83,60.17 32.86,59.14 32.86,58.96 33.23,58.59 33.42,58.59 33.66,58.34 33.66,57.73 v1(33.35,57.42)
  BOTTOM w0.14: P8.65 27,66.33 26.75,66.09 v1(26.5,66.09)
DAI1_PIN09: length 17
  TOP w0.14: U1.Y18 v1(35.75,57.42)
  L5_SIG2 w0.114: v1(27.5,66.55) 27.96,66.55 28.32,66.19 28.32,64.97 31.22,62.08 33.91,62.08 35.64,60.35 35.64,59.72 35.36,59.44 35.36,57.81 v1(35.75,57.42)
  BOTTOM w0.14: P8.67 v1(27.5,66.55)
DAI1_PIN10: length 14.2
  TOP w0.14: U1.AB21 v1(33.35,59.02)
  L5_SIG2 w0.114: v1(27.5,66.09) 27.24,66.09 27.13,65.98 27.13,64.8 30.63,61.29 32.49,61.29 33.35,60.43 v1(33.35,59.02)
  BOTTOM w0.14: v1(27.5,66.09) 27.75,66.09 28,66.33 P8.69
DAI1_PIN11: length 18.1
  TOP w0.14: P8.52 23.75,66.79 23.85,66.69 23.85,65.93 v1(23.5,65.58) ; U1.AB20 33.62,59.55 v1(32.97,59.55)
  L3_SIG1 w0.114: v1(23.5,65.58) 23.89,65.58 24,65.47 24,63.4 27.94,59.46 32.64,59.46 v1(32.97,59.55)
DAI1_PIN12: length 19.6
  TOP w0.14: P8.54 24.25,66.84 24.13,66.73 24.13,65.71 v1(23.5,65.07) ; U1.W20 v1(34.15,56.62)
  L3_SIG1 w0.114: v1(34.15,56.62) 34.07,56.96 33.76,57.28 33.76,57.63 33.57,57.82 32.43,57.82 31.8,58.45 28.45,58.45 23.5,63.4 v1(23.5,65.07)
DAI1_PIN13: length 21
  TOP w0.14: U1.V19 v1(34.95,55.82) ; v1(24.5,65.58) 24.85,65.93 24.85,66.69 24.75,66.79 P8.56
  L3_SIG1 w0.114: v1(34.95,55.82) 34.84,56.15 34.56,56.44 34.56,58.74 33.71,59.59 33.71,59.94 33.3,60.34 32.64,60.34 32.39,60.1 28.24,60.1 24.87,63.47 24.87,65.47 24.75,65.58 v1(24.5,65.58)
DAI1_PIN14: length 18.3
  TOP w0.14: P8.58 25.25,66.84 25.13,66.73 25.13,65.71 v1(24.5,65.07) ; U1.AA20 v1(34.15,58.22)
  L3_SIG1 w0.114: v1(34.15,58.22) 34.15,58.74 33.38,59.51 33.38,59.82 33.17,60.03 32.77,60.03 32.52,59.78 28.11,59.78 24.5,63.39 v1(24.5,65.07)
DAI1_PIN15: length 18.8
  TOP w0.14: P8.60 25.75,66.79 25.85,66.69 25.85,65.93 v1(25.5,65.58) ; U1.Y19 v1(34.95,57.42)
  L3_SIG1 w0.114: v1(25.5,65.58) 25.23,65.58 25.12,65.47 25.12,64.92 28.88,61.16 33.12,61.16 34.04,60.25 34.04,59.66 35.33,58.37 35.33,57.8 v1(34.95,57.42)
DAI1_PIN16: length 28.4
  TOP w0.14: v1(25.5,65.07) 26.13,65.71 26.13,66.73 26.25,66.84 P8.62 ; U1.U19 v1(34.95,55.02)
  L3_SIG1 w0.114: v1(25.5,65.07) 25.89,65.46 25.89,66.75 26.09,66.95 27.71,66.95 28.02,66.65 28.02,64.67 30.25,62.44 34.23,62.44 36.96,59.72 36.96,54.92 36.66,54.62 U1.U19 v1(34.95,55.02)
